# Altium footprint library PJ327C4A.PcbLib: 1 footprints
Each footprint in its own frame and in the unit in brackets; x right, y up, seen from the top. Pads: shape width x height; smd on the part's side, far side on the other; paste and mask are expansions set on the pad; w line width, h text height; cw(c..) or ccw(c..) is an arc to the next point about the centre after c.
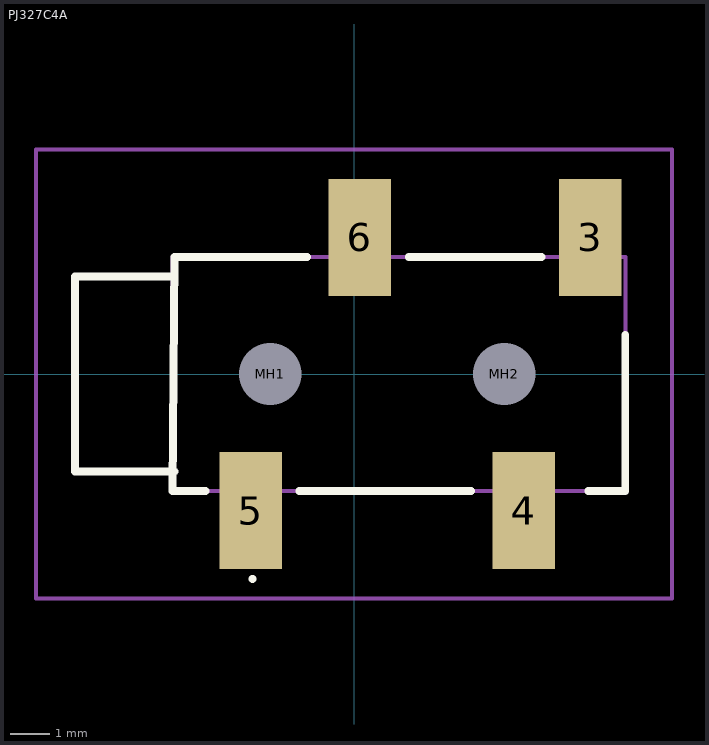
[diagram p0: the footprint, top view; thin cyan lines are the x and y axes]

## PJ327C4A [mm]
pads (6):
  rect 1.6x3 smd: 3(6.05,3.5) 4(4.35,-3.5) 5(-2.65,-3.5) 6(0.15,3.5)
  round 0.8 hole 1.6 unplated: MH1(-2.15,0) MH2(3.85,0)
Top Overlay:
  lines w0.1: -2.6,-5.3 cw(c-2.6,-5.25) -2.6,-5.2 ; -2.6,-5.3 -2.6,-5.3 ; -2.6,-5.3 ccw(c-2.6,-5.25) -2.6,-5.2 ; -2.6,-5.2 -2.6,-5.2
  lines w0.2: -4.6,-2.5 -7.15,-2.5 -7.15,2.5 -4.6,2.5 ; -3.8,-3 -4.65,-3 -4.6,3 -1.2,3 ; -1.4,-3 3,-3 ; 1.4,3 4.8,3 ; 6,-3 6.95,-3 6.95,1
Mechanical 15:
  lines w0.1: -4.65,-2.5 -7.15,-2.5 -7.15,2.5 -4.65,2.5 ; -4.65,-3 6.95,-3 6.95,3 -4.65,3 -4.65,-3
Mechanical 20:
  lines w0.1: -8.15,-5.75 8.15,-5.75 8.15,5.75 -8.15,5.75 -8.15,-5.75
